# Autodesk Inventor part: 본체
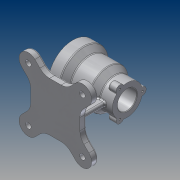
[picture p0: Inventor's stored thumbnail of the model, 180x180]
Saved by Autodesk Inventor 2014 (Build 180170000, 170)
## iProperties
Created: 2017-03
Part Number: 본체
Material: 알루미늄 6061
Document SubType Name: Modeling
Designer: Administrator
Mass: 1008.06 g
Surface Area: 842.102 cm^2
Volume: 371.977 cm^3
Density: 2.71 g/cm^3
Appearance: 알루미늄 - 평지
Author: Administrator
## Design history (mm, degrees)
sketch "스케치1"
  geometry: L1 (-50, 0)-(50, 0); L2 (-50, 0)-(-50, 45); L3 (-50, 45)-(-30, 45); L4 (-30, 45)-(-19, 36); L5 (-19, 36)-(15, 36); L6 (15, 36)-(27, 27.5); L7 (27, 27.5)-(50, 27.5); L8 (50, 27.5)-(50, 0); L9 (-50, 35)-(-30, 35); L10 (-27, 32)-(-27, 29); L11 (-24, 26)-(17, 26); L12 (20, 23)-(20, 20.5); L13 (23, 17.5)-(50, 17.5); A1 r 3 centre (-30, 32) between (-27, 32) and (-30, 35); A2 r 3 centre (-24, 29) between (-27, 29) and (-24, 26); A3 r 3 centre (17, 23) between (20, 23) and (17, 26); A4 r 3 centre (23, 20.5) between (20, 20.5) and (23, 17.5); 5 further points
  constraints: 26 end point, 8 point on circle, 8 point on line, 8 tangent, 5 parallel, 5 perpendicular, 4 centre point, 3 equal radius, 1 coincident, 1 horizontal, 1 midpoint
  dimensions: "d0" = 100 distance of L1.start L1.end; "d2" = 90 diameter of L3 L1; "d3" = 20 distance of L2.end L3.end; "d4" = 31 horizontal distance of L4.end L2.end; "d5" = 72 diameter of L5 L1; "d6" = 55 diameter of L7 L1; "d7" = 23 distance of L6.end L7.end; "d8" = 65 horizontal distance of L5.end L2.end; "d9" = 70 diameter of L9 L1; "d10" = 23 distance of L9.start point (-27, 35); "d12" = 52 diameter of L11 L1; "d13" = 47 distance of point (-27, 26) point (20, 26); "d14" = 35 diameter of L13 L1; "d15" = 3 radius of A1
revolve "회전1" sketch "스케치1" stored, may be unused: angle "d16" = 90 deg
chamfer "모따기1" distance "d17" = 1; stored, may be unused: second distance "d18" = 2, angle "d19" = 45 deg
sketch "스케치2"
  geometry: A1 r 27.5 centre (0, 0) between (0, 27.5) and (-6.943, 26.609) reference; A2 r 7 centre (0, 27.5) between (6.943, 26.609) and (-6.943, 26.609); A3 r 27.5 centre (0, 0) between (6.943, 26.609) and (-6.943, 26.609); 2 further points
  constraints: 8 point on circle, 2 centre point, 2 coincident, 1 vertical alignment
  dimensions: "d20" = 14 diameter of A2
extrude "돌출1" join sketch "스케치2" distance "d21" = 15; taper "d22" = 0 deg
fillet "모깎기2" dims "d24" = 3
fillet "모깎기3" dims "d25" = 1
hole "구멍1" sketch "스케치2" diameter "d29" = 3.242; stored, may be unused: countersink angle "d33" = 90 deg, drill point angle "d35" = 118 deg; dims "d30" = 9, "d31" = 4, "d32" = 2, "d34" = 11
fillet "모깎기4" dims "d39" = 3
sketch "스케치3"
  geometry: 2 further points
  constraints: 1 vertical alignment
  dimensions: "d40" = 40 distance of point (0, 0) point (0, 40)
hole "구멍2" sketch "스케치3" at (0, 40) diameter "d41" = 3.242; stored, may be unused: countersink angle "d45" = 90 deg, drill point angle "d47" = 118 deg; dims "d42" = 9, "d43" = 4, "d44" = 2, "d46" = 11
node "작업 평면1"
sketch "스케치4"
  geometry: C1 r 5 at (0, 0); 1 further point
  constraints: 1 centre point, 1 coincident
  dimensions: "d52" = 10 diameter of C1
extrude "돌출2" join sketch "스케치4" stored distance "d53" = 15; taper "d54" = 0 deg
fillet "모깎기5" dims "d55" = 3
hole "구멍3" diameter "d58" = 4.134; stored, may be unused: countersink angle "d62" = 90 deg, drill point angle "d64" = 118 deg; dims "d56" = 10, "d57" = 10, "d59" = 9, "d60" = 4, "d61" = 2, "d63" = 11
node "작업 평면2"
sketch "스케치5" dims "d66" = 140
  geometry: L1 (-45, -45)-(45, 45); L2 (45, -45)-(-45, 45); L3 (-45, 45)-(49.497, -49.497); L4 (-45, 45)-(-49.497, 49.497); L5 (45, 45)-(-45, -45); L6 (-45, -45)-(-49.497, -49.497); L7 (45, 45)-(49.497, 49.497); L8 (28.281, 52.322)-(37.477, 61.518); L9 (52.322, 28.281)-(61.518, 37.477); L10 (-10.603, -45)-(10.603, -45); L11 (45, -10.603)-(45, 10.603); L12 (10.603, 45)-(-10.603, 45); L13 (-45, 10.603)-(-45, -10.603); L14 (-45, -45)-(45, 45); L15 (45, -45)-(-45, 45); L16 (61.518, -37.477)-(52.322, -28.281); L17 (-28.281, 52.322)-(-37.477, 61.518); L18 (37.477, -61.518)-(28.281, -52.322); L19 (-52.322, 28.281)-(-61.518, 37.477); L20 (57.021, 32.979)-(52.322, 28.281); L21 (-28.281, -52.322)-(-37.477, -61.518); L22 (-61.518, -37.477)-(-52.322, -28.281); C1 r 5 at (-49.497, 49.497); C2 r 5 at (49.497, 49.497); C3 r 5 at (49.497, -49.497); C4 r 5 at (-49.497, -49.497); A1 r 17 centre (-49.497, 49.497) between (-37.477, 61.518) and (-61.518, 37.477); A2 r 17 centre (49.497, 49.497) between (61.518, 37.477) and (37.477, 61.518); A3 r 17 centre (49.497, -49.497) between (37.477, -61.518) and (61.518, -37.477); A4 r 17 centre (-49.497, -49.497) between (-61.518, -37.477) and (-37.477, -61.518); A5 r 25 centre (10.603, 70) between (10.603, 45) and (28.281, 52.322); A6 r 25 centre (70, 10.603) between (52.322, 28.281) and (45, 10.603); A7 r 25 centre (-10.603, 70) between (-28.281, 52.322) and (-10.603, 45); A8 r 25 centre (-70, 10.603) between (-45, 10.603) and (-52.322, 28.281); A9 r 25 centre (70, -10.603) between (45, -10.603) and (52.322, -28.281); A10 r 25 centre (10.603, -70) between (28.281, -52.322) and (10.603, -45); A11 r 25 centre (-70, -10.603) between (-52.322, -28.281) and (-45, -10.603); A12 r 25 centre (-10.603, -70) between (-10.603, -45) and (-28.281, -52.322); 18 further points
  constraints: 44 end point, 34 point on circle, 16 centre point, 16 tangent, 11 parallel, 9 coincident, 7 point on line, 5 collinear, 4 equal radius, 4 midpoint, 1 horizontal, 1 perpendicular, 12 other
  dimensions: "d67" = 90 distance of L2.end L1.end; "d68" = 90 distance of L1.end L2.start; "d69" = 34 diameter of A1; "d71" = 34 diameter of A2; "d72" = 34 diameter of A3; "d73" = 34 diameter of A4; "d75" = 10 diameter of C1; "d76" = 10 diameter of C2; "d77" = 10 diameter of C3; "d78" = 10 diameter of C4; "d112" = 90 distance of L15.end L1.end; "d113" = 90 distance of L1.end L15.start; "d114" = 25 radius of A5; "d117" = 25 radius of A7; "d118" = 25 radius of A8; "d121" = 25 radius of A11
extrude "돌출3" join sketch "스케치5" distance "d79" = 12; taper "d80" = 0 deg
extrude "돌출4" cut sketch "스케치5" stored distance "d81" = 12; taper "d82" = 0 deg
sketch "스케치6"
  geometry: L1 (-37, -4)-(37, -4); L2 (37, -4)-(37, 4); L3 (37, 4)-(-37, 4); L4 (-37, 4)-(-37, -4); L5 (-37, -4)-(37, 4); L6 (37, -4)-(-37, 4); 5 further points
  constraints: 12 end point, 6 midpoint, 2 parallel, 1 horizontal, 1 horizontal alignment, 1 perpendicular, 1 vertical alignment
  dimensions: "d83" = 8 distance between parallel lines of L1 L3; "d84" = 74 distance between parallel lines of L2 L4
extrude "돌출5" join sketch "스케치6" stored distance "d85" = 12; taper "d86" = 0 deg
sketch "스케치7"
  geometry: L1 (-70, -66.497)-(-70, -12.842) reference; L2 (-70, 12.842)-(-70, 66.497) reference; L3 (-31.096, -18.14)-(-70, -25); L4 (35.425, 6.411)-(-70, 25); A1 r 36 centre (0, 0) between (-35.777, -4) and (-35.777, 4) reference; 5 further points; 2 other entities
  constraints: 4 end point, 2 point on circle, 4 other
  dimensions: "d87" = 25 vertical distance of point (0, 0) L3.end; "d88" = 25 vertical distance of point (0, 0) L4.end (= d87); "d89" = 100 deg angle of L1 L3; "d90" = 100 deg dimension on L4 (= d89)
feature "리브1" dims "d91" = 1, "d92" = 8, "d93" = 0, "d94" = 0, "d95" = 1, "d96" = 1
feature "리브2" dims "d97" = 1, "d98" = 8, "d99" = 0, "d100" = 0, "d101" = 1, "d102" = 1
fillet "모깎기6" dims "d103" = 3
fillet "모깎기7" dims "d104" = 3
fillet "모깎기8" dims "d105" = 3
fillet "모깎기9" dims "d106" = 3
sketch "스케치8"
  geometry: L1 (45, -12.842)-(45, 12.842) reference; 2 further points
  constraints: 1 vertical alignment, 1 other
  dimensions: "d107" = 35 distance of point (0, -35) point (0, 0)
feature "엠보싱1" sketch "스케치8" dims "d108" = 0.5, "d109" = 0
node "솔리드1"
pattern_circular "원형 패턴1" dims "d27" = 360 deg
pattern_circular "원형 패턴2" dims angle "d37" = 360 deg
pattern_circular "원형 패턴3" dims angle "d49" = 360 deg
other parameters: "d110" = 17, "d111" = 17, "d115" = 17, "d116" = 17, "d119" = 17, "d120" = 17
